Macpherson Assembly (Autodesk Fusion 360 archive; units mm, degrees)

design "Macpherson Assembly" references "Wheel Hub Assembly"
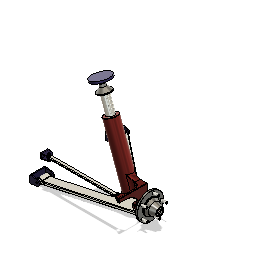
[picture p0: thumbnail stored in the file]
sketch "Sketch1" plane through (0, 0, 0) normal (1, 0, 0) x axis (0, 0, -1)
  line L1 (-40, 20) -> (40, 20)
  line L2 (-40, -20) -> (-40, 20)
  line L3 (40, -20) -> (-40, -20)
  line L4 (40, 20) -> (40, -20)
  line L5 (-40, -20) -> (40, 20)
  line L6 (40, -20) -> (-40, 20)
  point P6 (0, 0)
  point P1 (0, 0)
  horizontal L1
  perpendicular L1 L2
  parallel L1 L3
  parallel L2 L4
  coincident L5 P6
  coincident L6 P6
  coincident P1 P6
  dimension "d1" distance L2 L4 = 80
  dimension "d2" distance L1 L3 = 40
extrude "Extrude1" new body sketch "Sketch1" profile of L1 L2 L3 L4 along normal blind 5
sketch "Sketch2" plane through (0, 0, 0) normal (0, 0, 1) x axis (1, 0, 0)
  line L1 (37.374, 14.811) -> (5, 20)
  line L2 (37.374, -14.811) -> (5, -20)
  line L3 (5, -20) -> (5, 20)
  circle C1 centre (35, 0) radius 5
  arc A1 centre (35, 0) radius 15 clockwise from (37.374, 14.811) to (37.374, -14.811)
  point P1 (0, 0)
  point P3 (35, 0)
  concentric C1 A1
  tangent L1 A1
  tangent L2 A1
  horizontal P1 P3
  dimension "d7" distance P3 L3 = 30
  dimension "d8" diameter C1 = 10
  dimension "d9" radius A1 = 15
extrude "Extrude2" sketch "Sketch2" blind -5
extrude "Extrude3" sketch "Sketch2" blind 5
copy_paste_bodies "CopyPasteBodies2"
move "Move2"
work_plane "WorkPlane2" RotateAngle 20
work_plane "WorkPlane3" AlongDistance 400
sketch "Sketch4" plane through (-136.8081, 375.877, 12.125) normal (-0.342, 0.9397, 0) x axis (0, 0, 1)
  circle C1 centre (-112.125, 400) radius 50
  point P2 (-112.125, 400)
  point P3 (-12.125, 0)
  dimension "d21" distance P2 P3 = 100
  dimension "d22" distance P2 P3 = 400
  dimension "d23" diameter C1 = 100
extrude "Extrude4" new body sketch "Sketch4" along a picked direction blind 10
sketch "Sketch1" plane through (0, 0, 0) normal (0, 1, 0) x axis (1, 0, 0)
  line L1 (35, -35) -> (35, 435)
  line L2 (60, 425) -> (35, 425)
  line L3 (60, 375) -> (35, 375)
  line L4 (385.1588, 115.3869) -> (60, 375)
  line L5 (60, 25) -> (385.1588, 115.3869)
  line L6 (35, 25) -> (60, 25)
  line L7 (60, -25) -> (35, -25)
  line L8 (440.3565, 80.7306) -> (60, -25)
  line L9 (447.4788, 115.6294) -> (60, 425)
  line L10 (35, 375) -> (35, 425)
  line L11 (35, -25) -> (35, 25)
  line L12 (0, 0) -> (35, 0)
  line L13 (5, -35) -> (5, 35)
  closed curve K1 centre (235.6488, 100)
  arc A1 centre (435, 100) radius 20 clockwise from (447.4788, 115.6294) to (440.3565, 80.7306)
  circle C1 centre (435, 100) radius 17.5
  point P4 (35, 425)
  point P6 (435, 100)
  point P7 (235.6488, 100)
  point P8 (35, 375)
  point P12 (35, 25)
  point P13 (35, -25)
  point P17 (35, 0)
  point P1 (0, 0)
  point P18 (0, 0)
  point P19 (35, 400)
  point P21 (35, 0)
  point P20 (35, 400)
  point P14 (60, -25)
  vertical L1
  coincident L1 P4
  perpendicular L1 L2
  horizontal P6 P7
  coincident L1 P8
  perpendicular L1 L3
  coincident L1 P12
  perpendicular L1 L6
  coincident L1 P13
  perpendicular L1 L7
  tangent L8 A1
  tangent L9 A1
  equal L10 L11
  midpoint L11 P17
  coincident P1 P18
  horizontal L12
  midpoint L10 P19
  coincident P17 P21
  equal L6 L7
  equal L2 L3
  equal L3 L6
  coincident P19 P20
  parallel L4 L9
  parallel L5 L8
  concentric A1 C1
  dimension "d26" diameter A1 = 40
  dimension "d27" distance P20 P21 = 400
  dimension "d28" distance P12 P13 = 50
  dimension "d29" distance P14 L11 = 25
  dimension "d30" distance L1 L13 = 30
  dimension "d31" distance P6 P21 = 400
  dimension "d32" diameter C1 = 35
extrude "Extrude1" new body sketch "Sketch1" profile of L2 A1 L3 L4 L5 L6 L7 L8 L9 L10 L11 C1 distance 15
sketch "Sketch2" plane through (0, 0, 0) normal (0, 0, 1) x axis (1, 0, 0)
  line L1 (35, 7.5) -> (35, -7.5)
  circle C1 centre (35, 0) radius 15
  circle C2 centre (35, 0) radius 5
  point P2 (35, 0)
  midpoint P2 L1
  dimension "d35" diameter C1 = 30
extrude "Extrude2" add sketch "Sketch2" profile of C1 to an object Side2Offset 0
extrude "Extrude3" sketch "Sketch2" profile of C1 to an object
extrude "Extrude4" cut sketch "Sketch2" profile of L1 C2 no distance stored
sketch "Sketch1" plane through (0, 0, 0) normal (0, 0, 1) x axis (1, 0, 0)
ground "Ground1"
joint "Assemble1" alignAngle 0 alignOffsetX 0 alignOffsetY 0 alignOffsetZ 35
work_plane "WorkPlane4" AlongDistance 50
sketch "Sketch2" plane through (0, 0, 0) normal (1, 0, 0) x axis (0, 0, -1)
  line L1 (80.7306, 7.5) -> (115.6294, 7.5)
  line L2 (98.18, 7.5) -> (100, 512.6851)
  line L3 (115.6294, 20) -> (80.7306, 20)
  line L4 (-34.3706, 139.5804) -> (-6.7869, 139.5804)
  line L5 (-34.3706, 119.5804) -> (-34.3706, 139.5804)
  line L6 (-4.3706, 119.5804) -> (-34.3706, 119.5804)
  line L7 (-34.3706, 119.5804) -> (-6.7869, 139.5804)
  line L8 (-4.3706, 119.5804) -> (-34.3706, 139.5804)
  line L9 (80.7306, 34.4792) -> (80.7306, 20)
  line L10 (115.6294, 139.5804) -> (115.6294, 20)
  line L11 (-6.7869, 139.5804) -> (115.6294, 139.5804)
  closed curve K1 centre (100, 512.6851)
  arc A1 centre (-4.3706, 34.4792) radius 85.1012 clockwise from (-4.3706, 119.5804) to (80.7306, 34.4792)
  point P4 (100, 512.6851)
  point P5 (100, 512.6851)
  point P6 (98.18, 7.5)
  point P3 (80.7306, 7.5)
  point P7 (80.7306, 20)
  point P14 (-20, 130)
  point P9 (-20, 130)
  point P1 (0, 0)
  point P11 (-34.3706, 139.5804)
  point P12 (-34.3706, 119.5804)
  point P13 (-4.3706, 119.5804)
  coincident P4 P5
  midpoint L1 P6
  horizontal L3
  equal L1 L3
  vertical P3 P7
  horizontal L4
  perpendicular L4 L5
  parallel L4 L6
  coincident L7 P14
  coincident L8 P14
  coincident P9 P14
  perpendicular L3 L9
  tangent L9 A1
  tangent L6 A1
  perpendicular L3 L10
  horizontal L11
  dimension "d53" distance P1 L3 = 20
  dimension "d54" distance P1 P9 = 130
  dimension "d55" distance P1 P9 = 20
  dimension "d56" distance P11 P12 = 20
  dimension "d58" distance P12 P13 = 30
  dimension "d59" distance L5 L10 = 150
extrude "Extrude1" new body sketch "Sketch2" profile of L3 L4 L5 L6 L9 A1 L10 L11 blind 10 from offset 460
sketch "Sketch3" plane through (0, 20, 0) normal (0, -1, 0) x axis (1, 0, 0)
  line L1 (460, -115.6294) -> (460, -80.7306)
  line L2 (470, -115.6294) -> (460, -115.6294)
  line L3 (470, -80.7306) -> (470, -115.6294)
  line L4 (460, -80.7306) -> (470, -80.7306)
  line L5 (460, -115.6294) -> (460, -80.7306)
  line L6 (435.5912, -80.0087) -> (460, -80.7306)
  line L7 (438.7139, -119.6521) -> (460, -115.6294)
  circle C1 centre (435, -100) radius 17.5
  arc A1 centre (435, -100) radius 20 clockwise from (440.3565, -80.7306) to (447.4788, -115.6294)
  arc A2 centre (435, -100) radius 20 clockwise from (438.7139, -119.6521) to (435.5912, -80.0087)
  point P10 (440.3565, -80.7306)
  point P2 (460, -80.7306)
  point P13 (460, -80.7306)
  point P7 (460, -115.6294)
  point P15 (460, -115.6294)
  concentric C1 A2
  coincident P10 A2
  coincident P2 P13
  tangent L6 A2
  coincident P7 P15
  tangent L7 A2
extrude "Extrude2" add sketch "Sketch3" profile of L1 L5 C1 A2 L6 L7 to an object
sketch "Sketch4" plane through (0, 139.5804, 0) normal (0, 1, 0) x axis (-1, 0, 0)
  line L1 (-460, 34.3706) -> (-460, -115.6294)
  line L2 (-470, 34.3706) -> (-460, 34.3706)
  line L3 (-470, -115.6294) -> (-470, 34.3706)
  line L4 (-460, -115.6294) -> (-470, -115.6294)
  line L5 (-440.0679, 23.0697) -> (-460, 34.3706)
  line L6 (-440.0679, 5.6715) -> (-460, -5.6294)
  line L7 (-460, 34.3706) -> (-460, -5.6294)
  circle C1 centre (-445, 14.3706) radius 5
  arc A1 centre (-445, 14.3706) radius 10 clockwise from (-440.0679, 23.0697) to (-440.0679, 5.6715)
  point P3 (-460, 34.3706)
  point P7 (-460, 34.3706)
  point P9 (-460, -5.6294)
  point P11 (-460, 14.3706)
  point P6 (-445, 14.3706)
  point P12 (-445, 14.3706)
  coincident P3 P7
  tangent L5 A1
  coincident L1 P9
  tangent L6 A1
  midpoint L7 P11
  horizontal P6 P11
  concentric C1 A1
  dimension "d65" diameter A1 = 20
  dimension "d66" diameter C1 = 10
  dimension "d67" distance L7 P12 = 15
  dimension "d68" distance P6 P7 = 20
extrude "Extrude3" add sketch "Sketch4" profile of L1 A1 L5 L6 L7 C1 against normal blind 3
extrude "Extrude4" of existing geometry blind -3
joint "Assemble2" alignAngle 0 alignOffsetX 0 alignOffsetY 0 alignOffsetZ 20
work_plane "WorkPlane1" AlongDistance 150
sketch "Sketch7" plane through (290.372, 371.7312, -100) normal (0.342, -0.9397, 0) x axis (0, 0, -1)
  circle C1 centre (0, 0) radius 35
  point P1 (0, 0)
  point P2 (0, 0)
  coincident P1 P2
  dimension "d85" diameter C1 = 70
work_plane "WorkPlane2" AlongDistance -50
extrude "Extrude7" new body sketch "Sketch7" to an object
sketch "Sketch8" plane through (0, 0, -115.6294) normal (0, 0, -1) x axis (-1, 0, 0)
  line L1 (-470, 20) -> (-470, 139.5804)
  line L2 (-460, 20) -> (-470, 20)
  line L3 (-460, 34.4792) -> (-460, 20)
  line L4 (-460, 139.5804) -> (-460, 34.4792)
  line L5 (-470, 139.5804) -> (-460, 139.5804)
  line L6 (-433.2467, 70) -> (-460, 70)
  line L7 (-460, 139.5804) -> (-460, 70)
  line L8 (-406.7348, 139.5804) -> (-460, 139.5804)
  line L9 (-433.2467, 70) -> (-406.7348, 139.5804)
  point P8 (-460, 70)
  point P6 (-460, 139.5804)
  point P10 (-460, 139.5804)
  point P11 (-460, 139.5804)
  coincident L4 P8
  perpendicular L4 L6
  coincident P6 P10
  coincident P6 P11
  perpendicular L4 L8
  dimension "d89" distance P8 L9 = 25
extrude "Extrude8" add sketch "Sketch8" profile of L4 L6 L7 L8 L9 distance 15 from offset -15
shell "Shell1" innerThickness 15
work_plane "WorkPlane1" AlongDistance 0
sketch "Sketch1" plane through (290.372, 371.7312, -100) normal (-0.342, 0.9397, 0) x axis (0, 0, 1)
  circle C1 centre (0, 0) radius 20
extrude "Extrude1" new body sketch "Sketch1" blind -50 Side2Offset 50
work_axis "WorkAxis1"
work_plane "WorkPlane2" RotateAngle 0
sketch "Sketch2" plane through (239.069, 512.6851, -100) normal (0, 0, 1) x axis (1, 0, 0)
  line L1 (-1.6928, -53.825) -> (35.8949, -40.1442)
  line L2 (10.2606, -28.1908) -> (17.101, -46.9846)
  line L3 (-10.6752, -14.5272) -> (-8.7958, -13.8432)
  line L4 (-5.5449, -28.6226) -> (-10.6752, -14.5272)
  line L5 (-17.4983, -54.2569) -> (-5.5449, -28.6226)
  line L6 (-15.7882, -58.9553) -> (-17.4983, -54.2569)
  line L7 (-1.6928, -53.825) -> (-15.7882, -58.9553)
  line L8 (-1.9554, -32.637) -> (-8.7958, -13.8432)
  line L9 (10.2606, -28.1908) -> (-1.9554, -32.637)
  point P4 (17.101, -46.9846)
  point P3 (-1.6928, -53.825)
  point P9 (-1.6928, -53.825)
  point P1 (0, 0)
  point P7 (-17.4983, -54.2569)
  point P8 (-15.7882, -58.9553)
  point P5 (-10.6752, -14.5272)
  point P6 (-5.5449, -28.6226)
  midpoint L1 P4
  perpendicular L1 L2
  perpendicular L2 L3
  perpendicular L1 L4
  perpendicular L1 L6
  coincident P3 P9
  perpendicular L4 L7
  perpendicular L2 L9
  parallel L4 L8
  dimension "d100" distance L2 L4 = 15
  dimension "d103" distance P1 L3 = 10
  dimension "d104" distance P7 P8 = 5
  dimension "d106" distance P5 P6 = 15
  dimension "d108" distance L4 L8 = 2
  dimension "d109" distance L3 L9 = 20
  dimension "d144" distance P4 L6 = 35
revolve "Revolve1" sketch "Sketch2" AlongAngle 360
joint "Assemble3" alignAngle 0 alignOffsetX 0 alignOffsetY 0 alignOffsetZ -40
joint "Assemble4" alignAngle 0 alignOffsetX 0 alignOffsetY 0 alignOffsetZ 15
sketch "Sketch5" plane through (50, 0, 0) normal (1, 0, 0) x axis (0, 0, -1)
  line L1 (-35, 142.5) -> (5, 142.5)
  line L2 (-35, 117.5) -> (-35, 142.5)
  line L3 (5, 117.5) -> (-35, 117.5)
  line L4 (5, 142.5) -> (5, 117.5)
  line L5 (-35, 117.5) -> (5, 142.5)
  line L6 (5, 117.5) -> (-35, 142.5)
  point P6 (-15, 130)
  point P4 (-35, 117.5)
  point P5 (5, 117.5)
  point P3 (-35, 142.5)
  point P1 (0, 0)
  point P7 (0, 0)
  horizontal L1
  perpendicular L1 L2
  parallel L1 L3
  parallel L2 L4
  coincident L5 P6
  coincident L6 P6
  dimension "d118" distance P4 P5 = 40
  dimension "d119" distance P3 P4 = 25
  dimension "d120" distance P1 P6 = 130
  dimension "d121" distance P6 P7 = 15
extrude "Extrude5" new body sketch "Sketch5" profile of L1 L2 L3 L4 along normal blind 5
sketch "Sketch6" plane through (0, 142.5, 0) normal (0, 1, 0) x axis (-1, 0, 0)
  line L1 (-50, 35) -> (-50, -5)
  line L2 (-55, 35) -> (-50, 35)
  line L3 (-55, -5) -> (-55, 35)
  line L4 (-50, -5) -> (-55, -5)
  line L5 (-55, 35) -> (-55, -5)
  line L6 (-78.3672, 0.3828) -> (-55, -5)
  line L7 (-78.3672, 29.6172) -> (-55, 35)
  arc A1 centre (-75, 15) radius 15 clockwise from (-78.3672, 0.3828) to (-78.3672, 29.6172)
  circle C1 centre (-75, 15) radius 5
  point P5 (-55, -5)
  point P6 (-55, -5)
  point P4 (-55, 35)
  point P7 (-55, 35)
  point P9 (-55, 15)
  point P8 (-75, 15)
  point P11 (-55, 35)
  coincident P5 P6
  coincident P4 P7
  midpoint L3 P9
  horizontal P8 P9
  tangent L6 A1
  coincident P4 P11
  tangent L7 A1
  concentric A1 C1
  dimension "d124" diameter A1 = 30
  dimension "d125" distance L5 P8 = 20
  dimension "d126" diameter C1 = 10
extrude "Extrude6" add sketch "Sketch6" profile of L3 L5 A1 L6 L7 C1 against normal blind 3
extrude "Extrude7" sketch "Sketch6" profile of L3 L5 A1 L6 L7 C1 blind 3
work_plane "WorkPlane1"
sketch "Sketch1" plane through (72.5, 130, 15) normal (0, 1, 0) x axis (1, 0, 0)
  line L1 (372.517, -9.3706) -> (2.517, -10)
  line L2 (2.483, 10) -> (372.483, 10.6294)
  circle C1 centre (2.5, 0) radius 5
  circle C2 centre (372.5, 0.6294) radius 5
  arc A1 centre (372.5, 0.6294) radius 10 clockwise from (372.483, 10.6294) to (372.517, -9.3706)
  arc A2 centre (2.5, 0) radius 10 clockwise from (2.517, -10) to (2.483, 10)
  concentric C1 A2
  concentric C2 A1
  tangent L1 A1
  tangent L2 A2
  tangent L1 A2
  tangent L2 A1
  dimension "d132" diameter A2 = 20
  dimension "d133" diameter A1 = 20
extrude "Extrude1" new body sketch "Sketch1" distance 10
joint "Assemble5" alignAngle 0 alignOffsetX 0 alignOffsetY 0 alignOffsetZ 12.5
joint "Assemble6" alignAngle 0 alignOffsetX 0 alignOffsetY 0 alignOffsetZ -7
sketch "Sketch9" plane through (-85.505, 234.9232, 0) normal (-0.342, 0.9397, 0) x axis (0, 0, 1)
  circle C1 centre (-100, 400) radius 20
  circle C2 centre (-100, 400) radius 35
  circle C3 centre (-100, 400) radius 30
  concentric C1 C3
  dimension "d145" diameter C3 = 60
extrude "Extrude9" cut sketch "Sketch9" profile of C1 C3 to an object offset -10 from offset -10
sketch "Sketch3" plane through (-119.7071, 328.8924, 0) normal (0.342, -0.9397, 0) x axis (0, 0, -1)
  circle C1 centre (100, 400) radius 35
  circle C2 centre (100, 400) radius 20
  circle C3 centre (100, 400) radius 27.5
  concentric C1 C3
  dimension "d149" diameter C3 = 55
extrude "Extrude2" add sketch "Sketch3" profile of C2 C3 blind 5 from offset 150
component_insert "Component Insert"
position "Position1"
sketch "Sketch13" plane through (470, 0, 0) normal (1, 0, 0) x axis (0, 0, -1)
  line L1 (115.6294, 20) -> (80.7306, 20)
  line L2 (115.6294, 139.5804) -> (115.6294, 20)
  line L3 (-34.3706, 139.5804) -> (115.6294, 139.5804)
  line L4 (-34.3706, 119.5804) -> (-34.3706, 139.5804)
  line L5 (-4.3706, 119.5804) -> (-34.3706, 119.5804)
  line L6 (80.7306, 20) -> (80.7306, 34.4792)
  arc A1 centre (-4.3706, 34.4792) radius 85.1012 clockwise from (-4.3706, 119.5804) to (80.7306, 34.4792)
  closed curve K1 centre (95.0047, 59.9809)
extrude "Extrude10" add sketch "Sketch13" profile of L2 A1 L6 K1 to an object
work_axis "WorkAxis3"
sketch "Sketch15" plane through (475.0009, 59.9814, -95.0026) normal (0, 0, -1) x axis (-1, 0, 0)
  line L1 (-89, 0) -> (6, 0)
  line L2 (-89, 10) -> (-89, 0)
  line L3 (-69, 10) -> (-89, 10)
  line L4 (-15, 15) -> (-69, 10)
  line L5 (-5, 15) -> (-15, 15)
  line L6 (-5, 17) -> (-5, 15)
  line L7 (6, 17) -> (-5, 17)
  line L8 (6, 0) -> (6, 17)
  point P1 (0, 0)
  point P6 (-15, 15)
  point P7 (-5, 15)
  point P4 (-89, 10)
  point P5 (-69, 10)
  horizontal L1
  perpendicular L1 L2
  perpendicular L2 L3
  parallel L3 L5
  perpendicular L5 L6
  perpendicular L6 L7
  perpendicular L1 L8
  coincident P1 L1
  dimension "d158" distance L1 L7 = 17
  dimension "d159" distance L6 L8 = 11
  dimension "d160" distance L1 L5 = 15
  dimension "d161" distance P1 L8 = 6
  dimension "d162" distance P6 P7 = 10
  dimension "d163" distance L2 L8 = 95
  dimension "d164" distance L1 L3 = 10
  dimension "d165" distance P4 P5 = 20
revolve "Revolve2" sketch "Sketch15" AlongAngle 360
fillet "Fillet1" radius 10 30
fillet "Fillet2" radius 2
fillet "Fillet3" radius 2
fillet "Fillet4" radius 1 4 1
chamfer "Chamfer1" distance 3
thread "Thread1"
fillet "Fillet1" radius 3 50 20
fillet "Fillet1" radius 3
fillet "Fillet1" radius 1
joint "Assemble7" alignAngle 0 alignOffsetX 0 alignOffsetY 0 alignOffsetZ 0
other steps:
base_feature "Base Feature"
create_component "CreateComponent1"
create_component "CreateComponent2"
create_component "CreateComponent3"
joint_origin "JointOrigin1"
joint_origin "JointOrigin1"
joint_origin "JointOrigin1"
joint_origin "JointOrigin2"
create_component "CreateComponent4"
joint_origin "JointOrigin1"
joint_origin "JointOrigin2"
joint_origin "JointOrigin2"
joint_origin "JointOrigin2"
create_component "CreateComponent5"
joint_origin "JointOrigin1"
joint_origin "JointOrigin3"
joint_origin "JointOrigin2"
joint_origin "JointOrigin3"
joint_origin "JointOrigin6"

design "Wheel Hub"
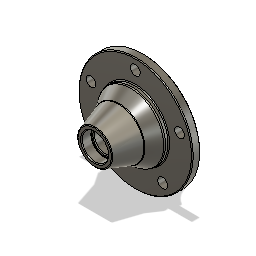
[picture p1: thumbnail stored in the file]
sketch "Sketch1" plane through (0, 0, 0) normal (1, 0, 0) x axis (0, 0, -1)
  line L1 (0, 30) -> (0, 25)
  line L2 (-15, 25) -> (0, 25)
  line L3 (-15, 18) -> (-15, 25)
  line L4 (-70, 13.1881) -> (-15, 18)
  line L5 (-70, 16.1881) -> (-70, 13.1881)
  line L6 (-82, 16.1881) -> (-70, 16.1881)
  line L7 (-82, 21.1881) -> (-82, 16.1881)
  line L8 (-52, 31.1881) -> (-82, 21.1881)
  line L9 (-37, 41.1881) -> (-52, 31.1881)
  line L10 (-32, 41.1881) -> (-37, 41.1881)
  line L11 (-32, 70) -> (-32, 41.1881)
  line L12 (-22, 70) -> (-32, 70)
  line L13 (-22, 45) -> (-22, 70)
  line L14 (-19, 45) -> (-22, 45)
  line L15 (-22.5, 0) -> (-1.75, 0)
  line L16 (0, 22.5) -> (0, 1.75)
  arc A1 centre (7.5092, 59.045) radius 30 clockwise from (0, 30) to (-19, 45)
  point P3 (0, 30)
  point P2 (0, 25)
  point P4 (-15, 25)
  point P5 (-15, 18)
  point P1 (0, 0)
  point P6 (-70, 13.1881)
  point P7 (-70, 16.1881)
  point P8 (-82, 16.1881)
  point P9 (-82, 21.1881)
  point P10 (-52, 31.1881)
  point P11 (-37, 41.1881)
  point P12 (-32, 41.1881)
  point P13 (-32, 70)
  point P14 (-22, 70)
  point P15 (-22, 45)
  point P16 (-19, 45)
  vertical L1
  perpendicular L1 L2
  perpendicular L2 L3
  perpendicular L2 L5
  perpendicular L5 L6
  perpendicular L6 L7
  perpendicular L2 L11
  perpendicular L7 L12
  perpendicular L12 L13
  perpendicular L13 L14
  horizontal L10
  coincident P3 L16
  dimension "d1" distance L2 L15 = 25
  dimension "d2" distance P2 P3 = 5
  dimension "d3" distance P4 P5 = 7
  dimension "d5" distance L3 L16 = 15
  dimension "d6" distance P1 P6 = 70
  dimension "d7" distance P7 P8 = 12
  dimension "d8" distance P8 P9 = 5
  dimension "d9" distance P6 P7 = 3
  dimension "d10" distance L7 P10 = 30
  dimension "d11" distance P9 P10 = 10
  dimension "d12" distance P10 P11 = 15
  dimension "d13" distance P10 P11 = 10
  dimension "d14" distance P11 P12 = 5
  dimension "d15" distance P1 L12 = 70
  dimension "d16" distance P13 P14 = 10
  dimension "d18" distance P15 P16 = 3
  dimension "d19" distance P14 P15 = 25
  dimension "d20" radius A1 = 30
  dimension "d34" angle L4 L15 = 5
revolve "Revolve1" sketch "Sketch1" AlongAngle 360
sketch "Sketch2" plane through (0, 0, 32) normal (0, 0, 1) x axis (1, 0, 0)
  circle C1 centre (0, 0) radius 41.1881
  circle C2 centre (0, 0) radius 70
  point P1 (0, 0)
  point P3 (0, 57.15)
  vertical P1 P3
  dimension "d22" distance P1 P3 = 57.15 (= "( 114.3 / 2 ) * 1 mm")
hole "Hole1" HoleDepth 5 HoleDiameter 12 TipAngle 118
circular_pattern "C-Pattern1" TotalAngle 360
fillet "Fillet1" radius 1 3 0.5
